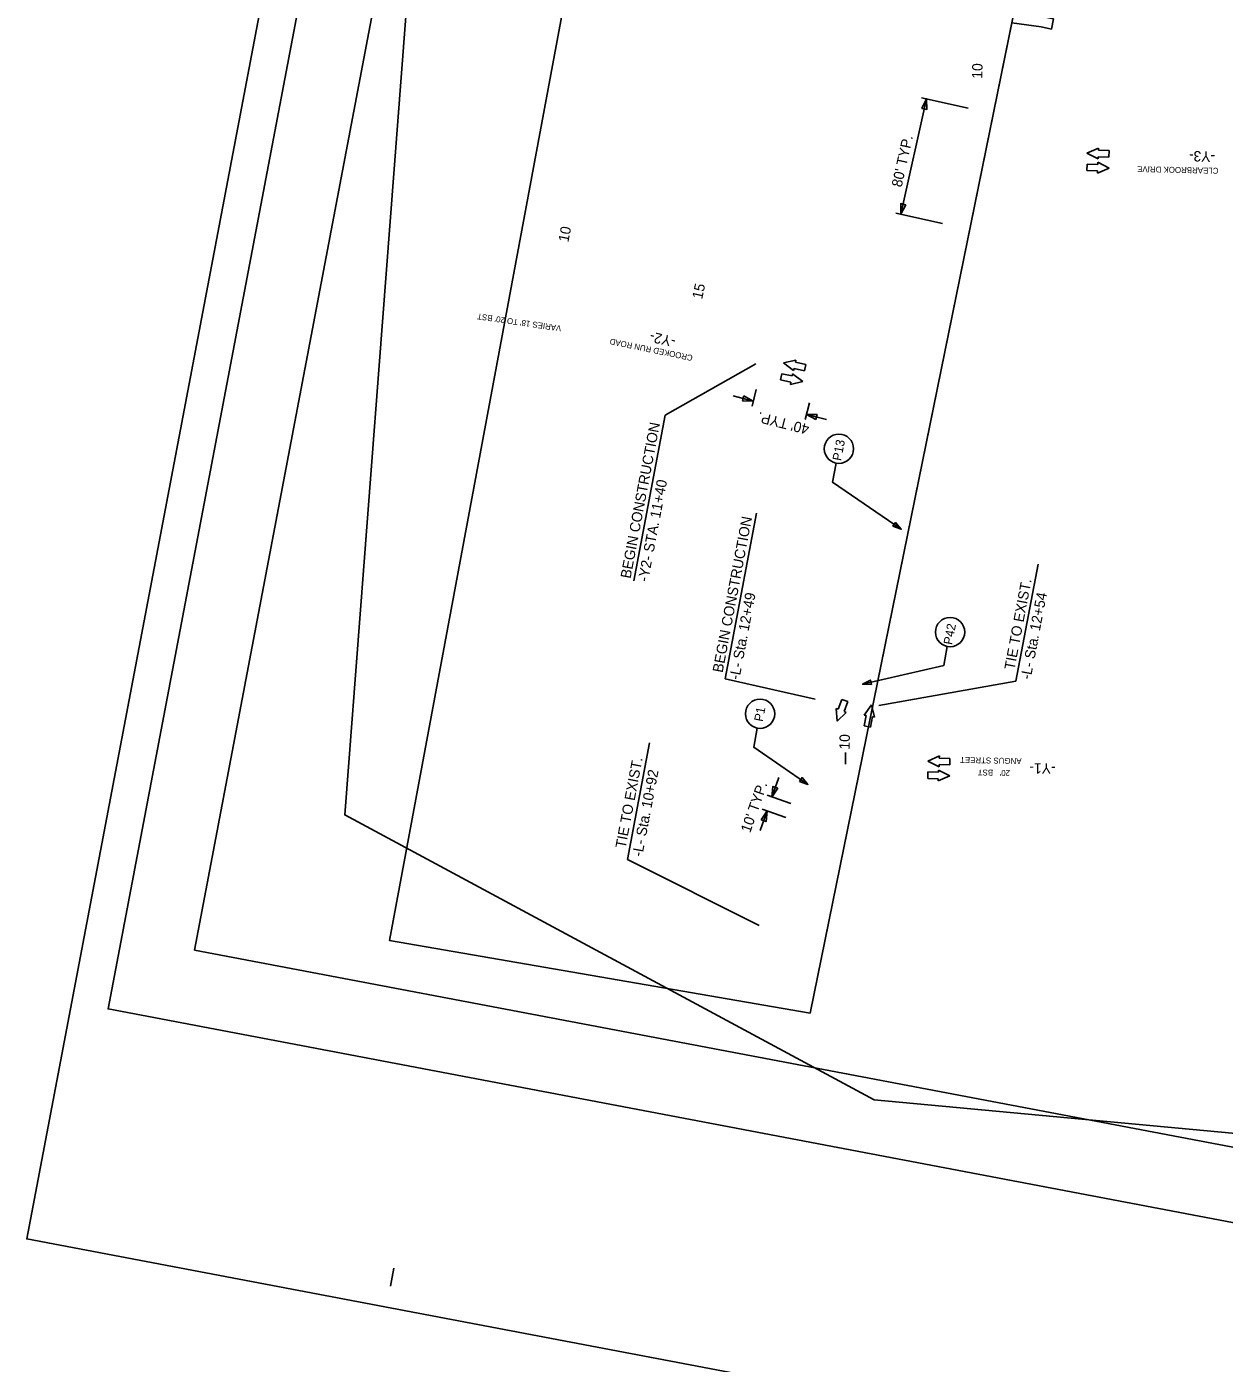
# Model space of a CAD drawing. Extents: x 1615680 to 1617075, y 898420 to 901376.
# Drawn here: x 1615680 to 1616489, y 899426 to 900330 of the extents above; entities that cross this region are included whole.
import ezdxf

# ---------------------------------------------------------------- set-up
doc = ezdxf.new("R2010")
doc.units = 0
for name, color, linetype in [('Default', 7, 'Continuous'), ('DEV BORDER CELL', 7, 'Continuous'), ('DEV DIRECTION OF TRAFFIC FLOW ARROW CELL', 7, 'Continuous'), ('Prop DSN Text', 7, 'Continuous'), ('Prop Horizontal Alignment Tick Label', 7, 'Continuous'), ('Prop Horizontal Alignment Tick Large', 7, 'Continuous'), ('Scratch_Level_0', 7, 'Continuous'), ('Sheet Clip Boundary CELL', 7, 'Continuous'), ('Sheet Plot Border Outside CELL', 7, 'Continuous'), ('Text', 7, 'Continuous')]:
    doc.layers.add(name, color=color, linetype=linetype)

msp = doc.modelspace()

# ---------------------------------------------------------------- linework, layer by layer
at = {"layer": 'Default'}
for points in [[(1616226.9, 900034.55), (1616224.45, 900021.61), (1616270.84, 899989.84)], [(1616302, 899910.6), (1616299.54, 899897.66), (1616244.73, 899885.11)], [(1616173.57, 899855.4), (1616171.11, 899842.46), (1616207.74, 899817.38)]]:
    msp.add_lwpolyline(points, dxfattribs=at)
for points in [[(1616265.18, 899991.83), (1616270.84, 899989.84), (1616266.94, 899994.39)], [(1616250.73, 899884.89), (1616244.73, 899885.11), (1616250.03, 899887.91)], [(1616202.08, 899819.37), (1616207.74, 899817.38), (1616203.83, 899821.94)]]:
    msp.add_lwpolyline(points, close=True, dxfattribs=at)
for centre in [(1616228.75, 900044.27), (1616303.85, 899920.32), (1616175.42, 899865.12)]:
    msp.add_circle(centre, 9.89, dxfattribs=at)
at = {"layer": 'DEV BORDER CELL'}
for p, q in [((1615734.93, 899666.51), (1615734.93, 899666.51)), ((1615925.64, 899478.13), (1615927.97, 899490.41))]:
    msp.add_line(p, q, dxfattribs=at)
msp.add_lwpolyline([(1616014.55, 901139.21), (1615734.74, 899665.53), (1616766.32, 899469.67), (1617046.12, 900943.35)], close=True, dxfattribs=at)
at = {"layer": 'DEV DIRECTION OF TRAFFIC FLOW ARROW CELL'}
for p, q in [((1616404.21, 900247.51), (1616396.34, 900244.1)), ((1616396.34, 900244.1), (1616404.21, 900247.51)), ((1616396.34, 900244.1), (1616403.98, 900240.21)), ((1616403.98, 900240.21), (1616396.34, 900244.1)), ((1616403.98, 900240.21), (1616404.03, 900241.69)), ((1616404.03, 900241.69), (1616403.98, 900240.21)), ((1616404.03, 900241.69), (1616411.22, 900241.46)), ((1616411.22, 900241.46), (1616404.03, 900241.69)), ((1616404.16, 900246.03), (1616404.21, 900247.51)), ((1616404.21, 900247.51), (1616404.16, 900246.03)), ((1616411.36, 900245.8), (1616404.16, 900246.03)), ((1616404.16, 900246.03), (1616411.36, 900245.8)), ((1616411.22, 900241.46), (1616411.36, 900245.8)), ((1616411.36, 900245.8), (1616411.22, 900241.46)), ((1616396.44, 900236.72), (1616396.31, 900232.37)), ((1616396.31, 900232.37), (1616396.44, 900236.72)), ((1616396.31, 900232.37), (1616403.5, 900232.14)), ((1616403.5, 900232.14), (1616396.31, 900232.37)), ((1616403.64, 900236.49), (1616396.44, 900236.72)), ((1616396.44, 900236.72), (1616403.64, 900236.49)), ((1616403.46, 900230.67), (1616411.32, 900234.07)), ((1616411.32, 900234.07), (1616403.46, 900230.67)), ((1616403.5, 900232.14), (1616403.46, 900230.67)), ((1616403.46, 900230.67), (1616403.5, 900232.14)), ((1616403.69, 900237.97), (1616403.64, 900236.49)), ((1616403.64, 900236.49), (1616403.69, 900237.97)), ((1616411.32, 900234.07), (1616403.69, 900237.97)), ((1616403.69, 900237.97), (1616411.32, 900234.07)), ((1616199.63, 900104.26), (1616191.29, 900102.3)), ((1616191.29, 900102.3), (1616199.63, 900104.26)), ((1616199.32, 900102.81), (1616199.63, 900104.26)), ((1616199.63, 900104.26), (1616199.32, 900102.81)), ((1616190.07, 900095.01), (1616189.17, 900090.76)), ((1616189.17, 900090.76), (1616190.07, 900095.01)), ((1616197.12, 900093.51), (1616190.07, 900095.01)), ((1616190.07, 900095.01), (1616197.12, 900093.51)), ((1616191.29, 900102.3), (1616198.11, 900097.11)), ((1616198.11, 900097.11), (1616191.29, 900102.3)), ((1616197.42, 900094.96), (1616197.12, 900093.51)), ((1616197.12, 900093.51), (1616197.42, 900094.96)), ((1616204.25, 900089.77), (1616197.42, 900094.96)), ((1616197.42, 900094.96), (1616204.25, 900089.77)), ((1616198.11, 900097.11), (1616198.42, 900098.56)), ((1616198.42, 900098.56), (1616198.11, 900097.11)), ((1616198.42, 900098.56), (1616205.46, 900097.06)), ((1616205.46, 900097.06), (1616198.42, 900098.56)), ((1616206.36, 900101.31), (1616199.32, 900102.81)), ((1616199.32, 900102.81), (1616206.36, 900101.31)), ((1616205.46, 900097.06), (1616206.36, 900101.31)), ((1616206.36, 900101.31), (1616205.46, 900097.06)), ((1616189.17, 900090.76), (1616196.21, 900089.26)), ((1616196.21, 900089.26), (1616189.17, 900090.76)), ((1616195.9, 900087.81), (1616204.25, 900089.77)), ((1616204.25, 900089.77), (1616195.9, 900087.81)), ((1616196.21, 900089.26), (1616195.9, 900087.81)), ((1616195.9, 900087.81), (1616196.21, 900089.26)), ((1616228.17, 899868.14), (1616226.79, 899868.66)), ((1616226.79, 899868.66), (1616227.45, 899860.12)), ((1616230.72, 899874.87), (1616228.17, 899868.14)), ((1616234.79, 899873.32), (1616230.72, 899874.87)), ((1616232.23, 899866.59), (1616234.79, 899873.32)), ((1616250.75, 899871.2), (1616245.71, 899864.27)), ((1616252.88, 899862.9), (1616250.75, 899871.2)), ((1616227.45, 899860.12), (1616233.61, 899866.07)), ((1616233.61, 899866.07), (1616232.23, 899866.59)), ((1616245.71, 899864.27), (1616247.16, 899863.99)), ((1616247.16, 899863.99), (1616245.81, 899856.92)), ((1616250.08, 899856.11), (1616251.43, 899863.18)), ((1616251.43, 899863.18), (1616252.88, 899862.9)), ((1616245.81, 899856.92), (1616250.08, 899856.11)), ((1616296.62, 899836.57), (1616288.76, 899833.16)), ((1616288.76, 899833.16), (1616296.62, 899836.57)), ((1616288.76, 899833.16), (1616296.39, 899829.27)), ((1616296.39, 899829.27), (1616288.76, 899833.16)), ((1616296.57, 899835.09), (1616296.62, 899836.57)), ((1616296.62, 899836.57), (1616296.57, 899835.09)), ((1616303.77, 899834.87), (1616296.57, 899835.09)), ((1616296.57, 899835.09), (1616303.77, 899834.87)), ((1616303.63, 899830.52), (1616303.77, 899834.87)), ((1616303.77, 899834.87), (1616303.63, 899830.52)), ((1616288.86, 899825.78), (1616288.72, 899821.43)), ((1616288.72, 899821.43), (1616288.86, 899825.78)), ((1616296.05, 899825.55), (1616288.86, 899825.78)), ((1616288.86, 899825.78), (1616296.05, 899825.55)), ((1616295.87, 899819.73), (1616303.73, 899823.13)), ((1616303.73, 899823.13), (1616295.87, 899819.73)), ((1616296.1, 899827.03), (1616296.05, 899825.55)), ((1616296.05, 899825.55), (1616296.1, 899827.03)), ((1616303.73, 899823.13), (1616296.1, 899827.03)), ((1616296.1, 899827.03), (1616303.73, 899823.13)), ((1616296.39, 899829.27), (1616296.44, 899830.75)), ((1616296.44, 899830.75), (1616296.39, 899829.27)), ((1616296.44, 899830.75), (1616303.63, 899830.52)), ((1616303.63, 899830.52), (1616296.44, 899830.75)), ((1616288.72, 899821.43), (1616295.92, 899821.21)), ((1616295.92, 899821.21), (1616288.72, 899821.43)), ((1616295.92, 899821.21), (1616295.87, 899819.73)), ((1616295.87, 899819.73), (1616295.92, 899821.21))]:
    msp.add_line(p, q, dxfattribs=at)
at = {"layer": 'Prop DSN Text'}
for p, q in [((1616172.65, 900101.68), (1616111.38, 900066.91)), ((1616090.11, 899954.94), (1616111.38, 900066.91)), ((1616151.87, 899888.77), (1616173.13, 900000.74)), ((1616348.41, 899887.19), (1616363.41, 899966.17)), ((1616212.73, 899875.03), (1616151.87, 899888.77)), ((1616255.72, 899870.76), (1616348.41, 899887.19)), ((1616085.79, 899766.49), (1616100.79, 899845.47)), ((1616174.85, 899722.08), (1616085.79, 899766.49))]:
    msp.add_line(p, q, dxfattribs=at)
at = {"layer": 'Prop Horizontal Alignment Tick Large'}
msp.add_line((1616233.07, 899830.96), (1616233.23, 899838.95), dxfattribs=at)
at = {"layer": 'Scratch_Level_0'}
for points in [[(1616054.34, 901080.76), (1615793.19, 899705.33), (1616726.52, 899528.12), (1616890.46, 900391.55), (1616774.26, 900413.61), (1616871.48, 900925.61)], [(1616209.3, 899662.81), (1616429.94, 900746.4), (1616473.81, 900995.89), (1616176.29, 901060.7), (1615925.06, 899711.77)], [(1616209.3, 899662.81), (1616345.54, 900332.12), (1616365.47, 900329.48), (1616372.31, 900327.99), (1616373.8, 900334.83), (1616366.96, 900336.32), (1616342.58, 900347.76), (1616473.81, 900995.89), (1616176.29, 901060.7), (1615925.06, 899711.77)]]:
    msp.add_lwpolyline(points, close=True, dxfattribs=at)
at = {"layer": 'Sheet Clip Boundary CELL'}
msp.add_lwpolyline([(1616176.29, 901060.7), (1616913.78, 900900.04), (1616896.28, 900812.91), (1616872.94, 900688.21), (1616835.87, 900695.21), (1616753.94, 900262.18), (1616898.09, 900233.43), (1616663.91, 899565.73), (1616252.62, 899604.04), (1615894.68, 899796.73), (1615981.58, 900932.46), (1616145.94, 900899.57)], close=True, dxfattribs=at)
at = {"layer": 'Sheet Plot Border Outside CELL'}
for points in [[(1616760.47, 899304.87), (1615679.78, 899510.06), (1615994.65, 901168.43), (1617075.34, 900963.24)], [(1616760.47, 899304.87), (1617075.34, 900963.24), (1615994.65, 901168.43), (1615679.78, 899510.06)]]:
    msp.add_lwpolyline(points, close=True, dxfattribs=at)
at = {"layer": 'Text'}
for p, q in [((1616270.67, 900202.76), (1616288.02, 900280.86)), ((1616316.03, 900274.63), (1616284.6, 900281.61)), ((1616298.68, 900196.54), (1616267.25, 900203.52)), ((1616157.3, 900080), (1616170.87, 900076.56)), ((1616172.85, 900084.38), (1616170.01, 900073.17)), ((1616208.75, 900075.29), (1616205.91, 900064.08)), ((1616206.77, 900067.48), (1616220.34, 900064.04)), ((1616188.1, 899822.05), (1616183.46, 899808.84)), ((1616196.18, 899804.38), (1616180.16, 899809.99)), ((1616180.15, 899799.4), (1616175.52, 899786.19)), ((1616192.87, 899794.94), (1616176.85, 899800.56))]:
    msp.add_line(p, q, dxfattribs=at)
for points in [[(1616284.8, 900274.4), (1616288.02, 900280.86), (1616288.21, 900273.64)], [(1616273.9, 900209.21), (1616270.67, 900202.76), (1616270.48, 900209.97)], [(1616164.52, 900079.97), (1616170.87, 900076.56), (1616163.66, 900076.58)], [(1616213.12, 900064.06), (1616206.77, 900067.48), (1616213.98, 900067.45)], [(1616187.43, 899814.86), (1616183.46, 899808.84), (1616184.13, 899816.02)], [(1616176.19, 899793.37), (1616180.15, 899799.4), (1616179.49, 899792.22)]]:
    msp.add_lwpolyline(points, close=True, dxfattribs=at)

# ---------------------------------------------------------------- texts
at = {"layer": 'Default'}
for s, height, rotation, p in [('CLEARBROOK DRIVE', 4, 178.75092, (1616485.31, 900234.17)), ("VARIES 18' TO 20' BST", 4, 171.6581, (1616041.32, 900127.5)), ('CROOKED RUN ROAD', 4, 168.45796, (1616130.22, 900107.48)), ('P13', 6, 79.24933, (1616230.19, 900035.79)), ('P42', 6, 79.2494, (1616305.23, 899911.41)), ('P1', 6, 79.24933, (1616177.25, 899859.47)), ('ANGUS STREET', 4, 178.75092, (1616352.23, 899835.04)), ("20'   BST", 4, 178.72674, (1616344.42, 899826.98))]:
    msp.add_text(s, height=height, rotation=rotation, dxfattribs=at).set_placement(p)
at = {"layer": 'Prop DSN Text'}
for s, rotation, p in [('BEGIN CONSTRUCTION', 79.24933, (1616087.87, 899956.17)), ('-Y2- STA. 11+40', 79.24933, (1616099.66, 899953.93)), (' BEGIN CONSTRUCTION', 79.24933, (1616149.62, 899890)), ('TIE TO EXIST.', 79.2494, (1616347.36, 899894.44)), ('-L- Sta. 12+49', 79.24933, (1616161.41, 899887.76)), (' -L- Sta. 12+54', 79.2494, (1616357.82, 899885.39)), ('TIE TO EXIST.', 79.24933, (1616084.48, 899773.79)), (' -L- Sta. 10+92', 79.24933, (1616095.29, 899765.58))]:
    msp.add_text(s, height=7, rotation=rotation, dxfattribs=at).set_placement(p)
at = {"layer": 'Prop Horizontal Alignment Tick Label'}
for s, rotation, p in [('10', 88.56805, (1616325.6, 900294.39)), ('-Y3-', 178.07469, (1616483.1, 900245.07)), ('10', 78.83642, (1616045.82, 900183.62)), ('15', 77.70978, (1616136.26, 900144.99)), ('-Y2-', 167.14002, (1616118.92, 900119.64)), ('10', 88.56805, (1616235.94, 899840.82)), ('-Y1-', 179.34693, (1616375.22, 899831.55))]:
    msp.add_text(s, height=7, rotation=rotation, dxfattribs=at).set_placement(p)
at = {"layer": 'Text'}
for s, rotation, p in [("80' TYP.", 77.47442, (1616271.07, 900220.69)), ("40' TYP.", 165.79647, (1616209.22, 900060.5)), ("10' TYP.", 70.67108, (1616168.73, 899784.21))]:
    msp.add_text(s, height=7, rotation=rotation, dxfattribs=at).set_placement(p)

doc.saveas('drawing.dxf')
